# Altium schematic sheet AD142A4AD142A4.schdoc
size 127 x 101 mm
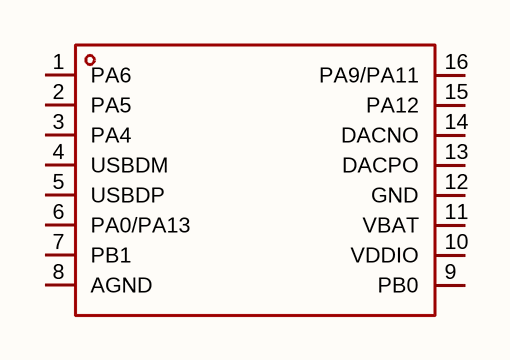
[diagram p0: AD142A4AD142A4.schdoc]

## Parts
U?  ad142a4  [SOP-16_L9.9-W3.9-P1.27-LS6.0-BL]  (value not drawn)

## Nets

Not connected (* = marked no-connect by the designer): U? 1(PA6) 2(PA5) 3(PA4) 4(USBDM) 5(USBDP) 6(PA0/PA13) 7(PB1) 8(AGND) 9(PB0) 10(VDDIO) 11(VBAT) 12(GND) 13(DACPO) 14(DACNO) 15(PA12) 16(PA9/PA11)

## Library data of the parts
U? = ad142a4: CPU内核:-;CPU最大主频:160MHz;CPU位数:32bit;; Manufacturer: JL(杰理); AddInBom: yes; ModelId: ed96d47c1e844792b3e705d722a1a1fa; ModelTransform: 389.763,236.22,0,0,0,0,0,0,0; CPU Maximum Speed: 160MHz; Core Size: 32bit; ADC (Bit): 16bit；10bit; DAC (Bit): 16bit; Voltage - Supply: 2V~5.5V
